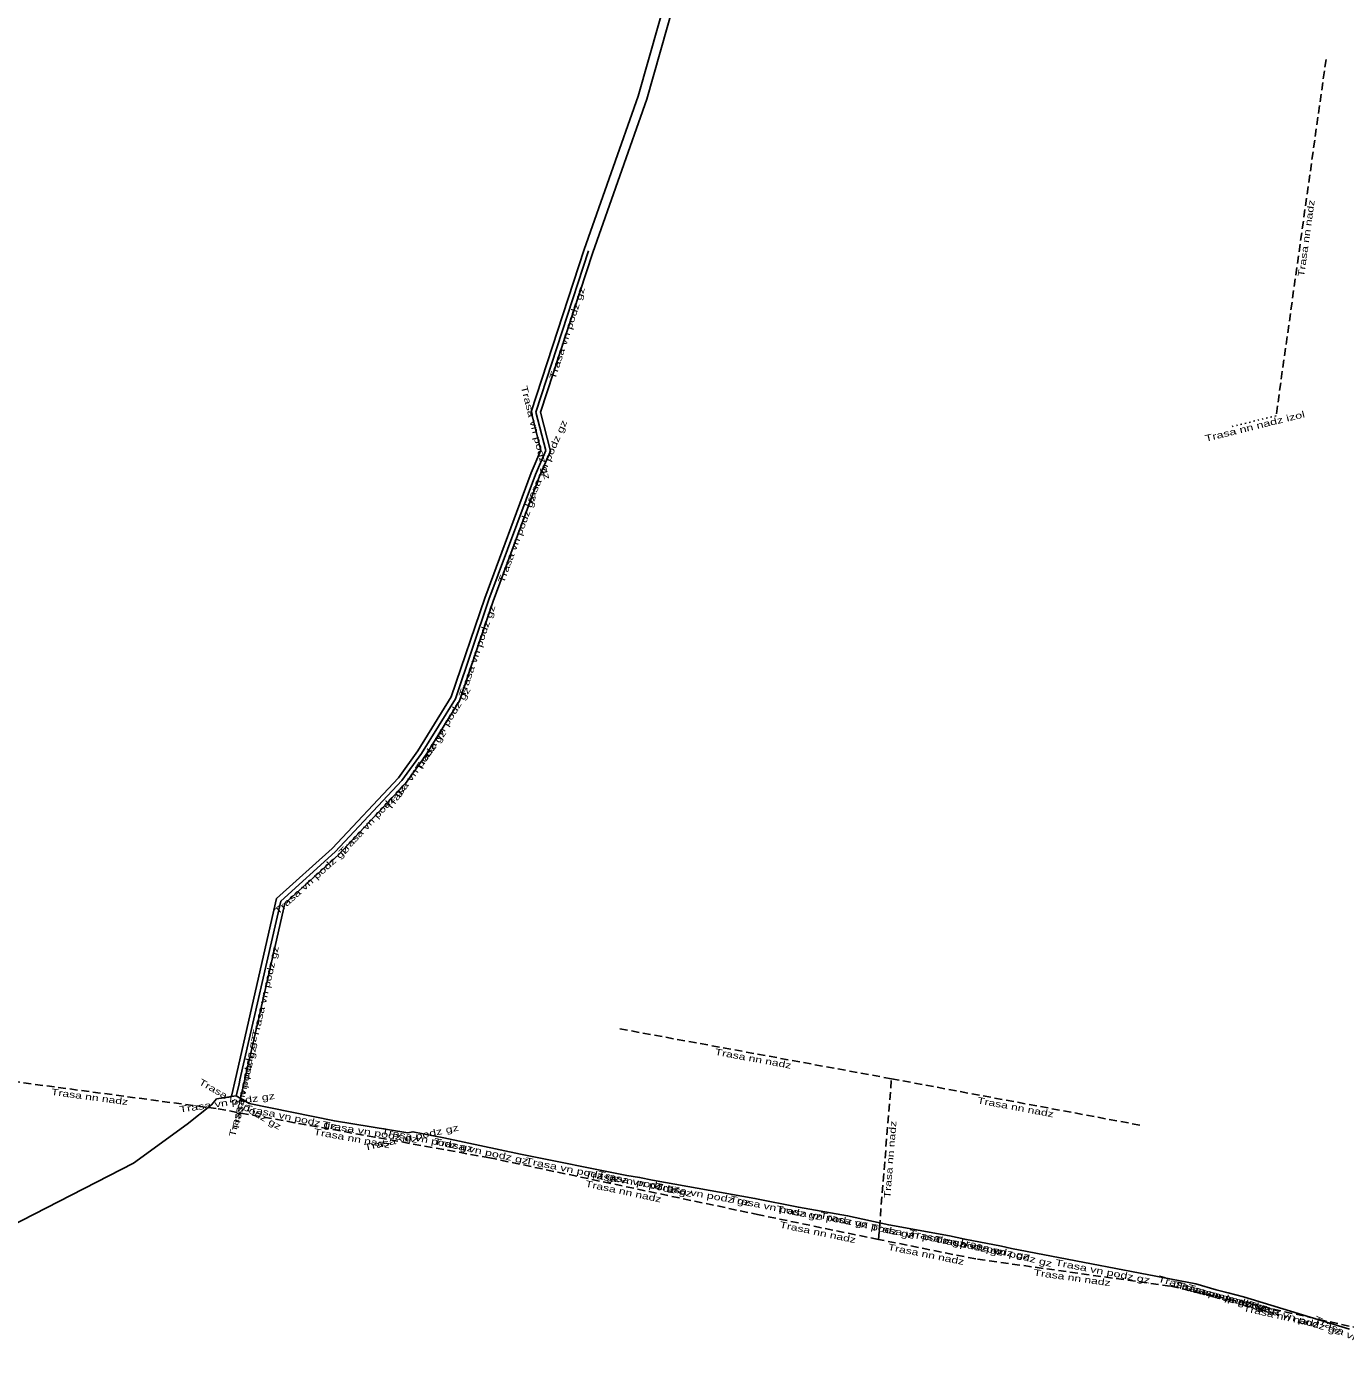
# Model space of a CAD drawing. Extents: x -733620 to -732615, y -1025255 to -1024617.
# Drawn here: x -733025.6 to -732923.9, y -1024815 to -1024711.1 of the extents above; entities that cross this region are included whole.
import ezdxf
from ezdxf.enums import TextEntityAlignment as Align

# ---------------------------------------------------------------- set-up
doc = ezdxf.new("R2010")
doc.units = 0
doc.header["$LTSCALE"] = 0.2
doc.linetypes.add('DOTTED', pattern=[1.5, 0.3, -1.2])
doc.linetypes.add('MEDIUM_DASHED', pattern=[4.5, 3, -1.5])
doc.layers.add('11', color=7, linetype='MEDIUM_DASHED', lineweight=25)
doc.layers.add('21', color=7, linetype='Continuous', lineweight=25)
doc.layers.add('20', color=7, linetype='Continuous')

msp = doc.modelspace()

# ---------------------------------------------------------------- linework, layer by layer
at = {"layer": '11'}
for p, q in [((-732925.37, -1024713.65), (-732929.22, -1024741.14)), ((-732958.9, -1024792.3), (-732980.1, -1024788.4)), ((-733011, -1024794.6), (-733030.43, -1024792)), ((-732959.9, -1024804.7), (-732958.9, -1024792.3)), ((-732958.9, -1024792.3), (-732939.6, -1024795.9)), ((-732989.9, -1024798.4), (-733011, -1024794.6)), ((-732969.1, -1024802.8), (-732989.9, -1024798.4)), ((-732959.9, -1024804.7), (-732969.1, -1024802.8)), ((-732952.4, -1024806.2), (-732959.9, -1024804.7)), ((-732937.4, -1024808.3), (-732952.4, -1024806.2)), ((-732920.07, -1024812.17), (-732937.4, -1024808.3))]:
    msp.add_line(p, q, dxfattribs=at)
at = {"layer": '11', "linetype": 'DOTTED'}
msp.add_line((-732929.22, -1024741.14), (-732932.7, -1024742), dxfattribs=at)
at = {"layer": '21'}
for p, q in [((-732982.283, -1024728.427), (-732986.334, -1024740.854)), ((-732986.334, -1024740.854), (-732985.579, -1024743.837)), ((-732985.579, -1024743.837), (-732986.377, -1024745.674)), ((-732986.377, -1024745.674), (-732989.958, -1024755.326)), ((-732989.958, -1024755.326), (-732992.551, -1024762.984)), ((-732992.551, -1024762.984), (-732995.159, -1024767.202)), ((-732995.159, -1024767.202), (-732996.671, -1024769.296)), ((-732996.671, -1024769.296), (-733001.815, -1024774.782)), ((-733001.815, -1024774.782), (-733006.028, -1024778.585)), ((-733006.028, -1024778.585), (-733009.172, -1024792.382)), ((-733009.24, -1024792.726), (-733009.455, -1024793.629)), ((-733009.172, -1024792.382), (-733009.24, -1024792.726)), ((-733009.455, -1024793.629), (-733010.985, -1024793.85)), ((-733009.455, -1024793.629), (-733008.463, -1024794.197)), ((-733008.463, -1024794.197), (-733001.883, -1024795.557)), ((-733001.883, -1024795.557), (-732996.222, -1024796.476)), ((-732996.222, -1024796.476), (-732995.827, -1024796.391)), ((-732995.827, -1024796.391), (-732993.434, -1024796.861)), ((-732993.434, -1024796.861), (-732987.515, -1024798.122)), ((-732987.515, -1024798.122), (-732979.308, -1024799.757)), ((-732979.308, -1024799.757), (-732978.337, -1024799.914)), ((-732978.337, -1024799.914), (-732977.336, -1024800.127)), ((-732977.336, -1024800.127), (-732969.433, -1024801.533)), ((-732969.433, -1024801.533), (-732966.079, -1024802.213)), ((-732966.079, -1024802.213), (-732962.281, -1024802.874)), ((-732962.281, -1024802.874), (-732959.104, -1024803.575)), ((-732959.104, -1024803.575), (-732954.423, -1024804.43)), ((-732954.423, -1024804.43), (-732953.229, -1024804.688)), ((-732953.229, -1024804.688), (-732950.419, -1024805.215)), ((-732950.419, -1024805.215), (-732949.626, -1024805.409)), ((-732935.422, -1024808.118), (-732949.626, -1024805.409)), ((-732933.834, -1024808.574), (-732935.422, -1024808.118)), ((-732932.912, -1024808.811), (-732933.834, -1024808.574)), ((-732931.743, -1024809.13), (-732932.912, -1024808.811)), ((-732923.565, -1024811.633), (-732931.743, -1024809.13))]:
    msp.add_line(p, q, dxfattribs=at)
for points in [[(-733010.985, -1024793.85), (-733009.838, -1024793.684), (-733009.796, -1024793.552), (-733009.513, -1024792.304), (-733006.345, -1024778.399), (-733002.06, -1024774.532), (-732996.942, -1024769.073), (-732995.45, -1024767.007), (-732992.87, -1024762.834), (-732990.288, -1024755.209), (-732986.702, -1024745.543), (-732985.948, -1024743.807), (-732986.698, -1024740.842), (-732982.614, -1024728.315), (-732978.449, -1024716.493), (-732975.26, -1024705.256)], [(-732974.59, -1024705.458), (-732977.781, -1024716.705), (-732981.952, -1024728.539), (-732985.97, -1024740.866), (-732985.21, -1024743.867), (-732986.052, -1024745.805), (-732989.628, -1024755.443), (-732992.232, -1024763.134), (-732994.868, -1024767.397), (-732996.4, -1024769.519), (-733001.57, -1024775.032), (-733005.711, -1024778.771), (-733008.831, -1024792.46), (-733009.114, -1024793.706), (-733009.14, -1024793.809), (-733008.463, -1024794.197)], [(-733124.635, -1024855.725), (-733102.986, -1024843.362), (-733092.656, -1024837.362), (-733060.022, -1024819.78), (-733038.504, -1024809.639), (-733017.396, -1024798.81), (-733013.231, -1024795.794), (-733011.375, -1024794.322), (-733010.985, -1024793.85)], [(-733008.463, -1024794.197), (-733001.883, -1024795.557), (-732996.222, -1024796.476), (-732995.827, -1024796.391), (-732993.434, -1024796.861), (-732987.515, -1024798.122), (-732979.308, -1024799.757), (-732978.337, -1024799.914), (-732977.336, -1024800.127), (-732969.433, -1024801.533), (-732966.079, -1024802.213), (-732962.281, -1024802.874), (-732959.104, -1024803.575), (-732954.423, -1024804.43), (-732953.229, -1024804.688), (-732950.419, -1024805.215), (-732949.626, -1024805.409), (-732935.422, -1024808.118), (-732933.834, -1024808.574), (-732931.743, -1024809.13), (-732923.565, -1024811.633)]]:
    msp.add_lwpolyline(points, dxfattribs=at)

# ---------------------------------------------------------------- texts
at = {"layer": '20'}
for s, rotation, width, p in [('Trasa nn nadz', 82.028, 1.4, (-732926.651, -1024727.4842)), ('Trasa vn podz gz', 71.945, 1.45, (-732983.6902, -1024734.841)), ('Trasa vn podz gz', 284.203, 1.45, (-732986.586, -1024742.5052)), ('Trasa nn nadz izol', 13.881, 1.45, (-732930.8035, -1024742.2003)), ('Trasa vn podz gz', 66.52, 1.45, (-732985.381, -1024745.0141)), ('Trasa vn podz gz', 69.645, 1.4, (-732987.5568, -1024750.7255)), ('Trasa vn podz gz', 71.294, 1.45, (-732990.6392, -1024759.3627)), ('Trasa vn podz gz', 58.271, 1.45, (-732993.3013, -1024765.434)), ('Trasa vn podz gz', 54.168, 1.45, (-732995.3879, -1024768.6289)), ('Trasa vn podz gz', 46.843, 1.4, (-732998.7683, -1024772.4835)), ('Trasa vn podz gz', 42.072, 1.45, (-733003.485, -1024777.1649)), ('Trasa vn podz gz', 77.163, 1.4, (-733006.9654, -1024785.627)), ('Trasa vn podz gz', 78.818, 1.45, (-733008.5681, -1024792.68)), ('Trasa vn podz gz', 76.608, 1.4, (-733008.7146, -1024793.3274)), ('Trasa nn nadz', 349.576, 1.4, (-732969.6167, -1024790.9887)), ('Trasa vn podz gz', 330.205, 1.4, (-733009.2817, -1024794.4765)), ('Trasa nn nadz', 352.378, 1.4, (-733020.8007, -1024793.9429)), ('Trasa vn podz gz', 8.219, 1.45, (-733010.1262, -1024794.3822)), ('Trasa nn nadz', 349.434, 1.4, (-732949.3683, -1024794.7385)), ('Trasa vn podz gz', 348.322, 1.4, (-733005.3041, -1024795.5128)), ('Trasa vn podz gz', 350.779, 1.45, (-732999.1566, -1024796.657)), ('Trasa vn podz gz', 12.144, 1.45, (-732995.8861, -1024797.0691)), ('Trasa nn nadz', 85.389, 1.4, (-732958.7513, -1024798.5516)), ('Trasa nn nadz', 349.791, 1.4, (-733000.5648, -1024797.1392)), ('Trasa vn podz gz', 348.888, 1.4, (-732994.7557, -1024797.2642)), ('Trasa vn podz gz', 347.973, 1.45, (-732990.6096, -1024798.1271)), ('Trasa vn podz gz', 348.733, 1.45, (-732983.5383, -1024799.5766)), ('Trasa vn podz gz', 350.815, 1.45, (-732978.9254, -1024800.4765)), ('Trasa vn podz gz', 347.987, 1.45, (-732977.9715, -1024800.6561)), ('Trasa nn nadz', 348.056, 1.4, (-732979.6342, -1024801.2356)), ('Trasa vn podz gz', 349.912, 1.45, (-732973.4983, -1024801.47)), ('Trasa vn podz gz', 348.539, 1.4, (-732967.8842, -1024802.5094)), ('Trasa vn podz gz', 350.127, 1.4, (-732964.2914, -1024803.1835)), ('Trasa vn podz gz', 347.557, 1.45, (-732960.8324, -1024803.8587)), ('Trasa nn nadz', 348.331, 1.4, (-732964.6311, -1024804.3869)), ('Trasa vn podz gz', 349.649, 1.45, (-732956.8794, -1024804.6416)), ('Trasa vn podz gz', 347.807, 1.45, (-732953.9623, -1024805.194)), ('Trasa nn nadz', 348.69, 1.4, (-732956.2765, -1024806.0865)), ('Trasa vn podz gz', 349.378, 1.45, (-732951.9436, -1024805.5907)), ('Trasa vn podz gz', 346.253, 1.45, (-732950.1769, -1024805.9438)), ('Trasa vn podz gz', 349.202, 1.45, (-732942.6453, -1024807.4013)), ('Trasa nn nadz', 352.03, 1.4, (-732944.9892, -1024807.8928)), ('Trasa vn podz gz', 343.978, 1.45, (-732934.8065, -1024808.9699)), ('Trasa vn podz gz', 345.584, 1.45, (-732933.5347, -1024809.3219)), ('Trasa vn podz gz', 345.11, 1.45, (-732933.3047, -1024809.3861)), ('Trasa vn podz gz', 344.737, 1.45, (-732932.4983, -1024809.5965)), ('Trasa vn podz gz', 342.982, 1.45, (-732927.8437, -1024811.0027)), ('Trasa nn nadz', 347.412, 1.4, (-732928.876, -1024810.8681)), ('Trasa vn podz gz', 334.455, 1.45, (-732922.9833, -1024812.6304))]:
    msp.add_text(s, height=0.5, rotation=rotation, dxfattribs=dict(at, width=width)).set_placement(p, align=Align.CENTER)

doc.saveas('drawing.dxf')
